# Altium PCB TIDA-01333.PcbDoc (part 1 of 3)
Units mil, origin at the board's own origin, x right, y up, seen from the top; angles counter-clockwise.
Board outline 6250 x 2150 mil, 4 copper layers (Top Layer, GND, VDD, Bottom Layer), stack 61.6 mil thick; 242 components, 144 nets, 711 pads, 252 vias.
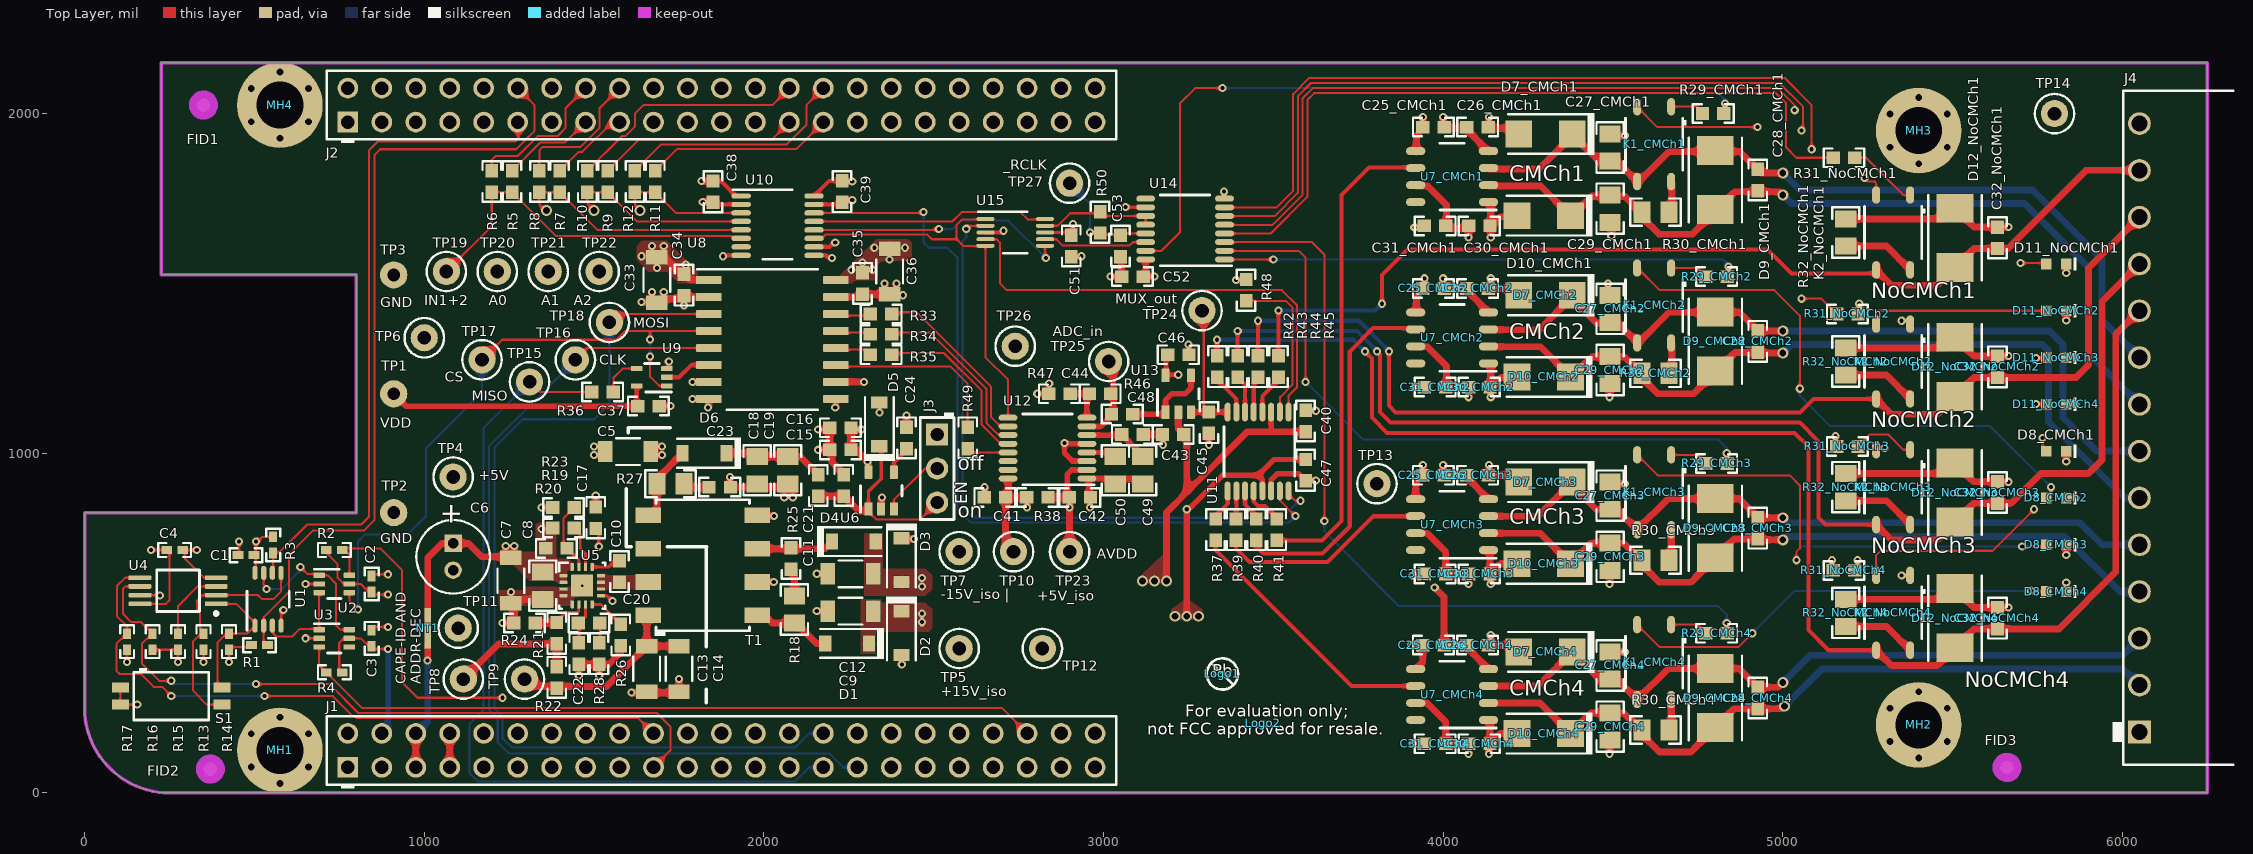
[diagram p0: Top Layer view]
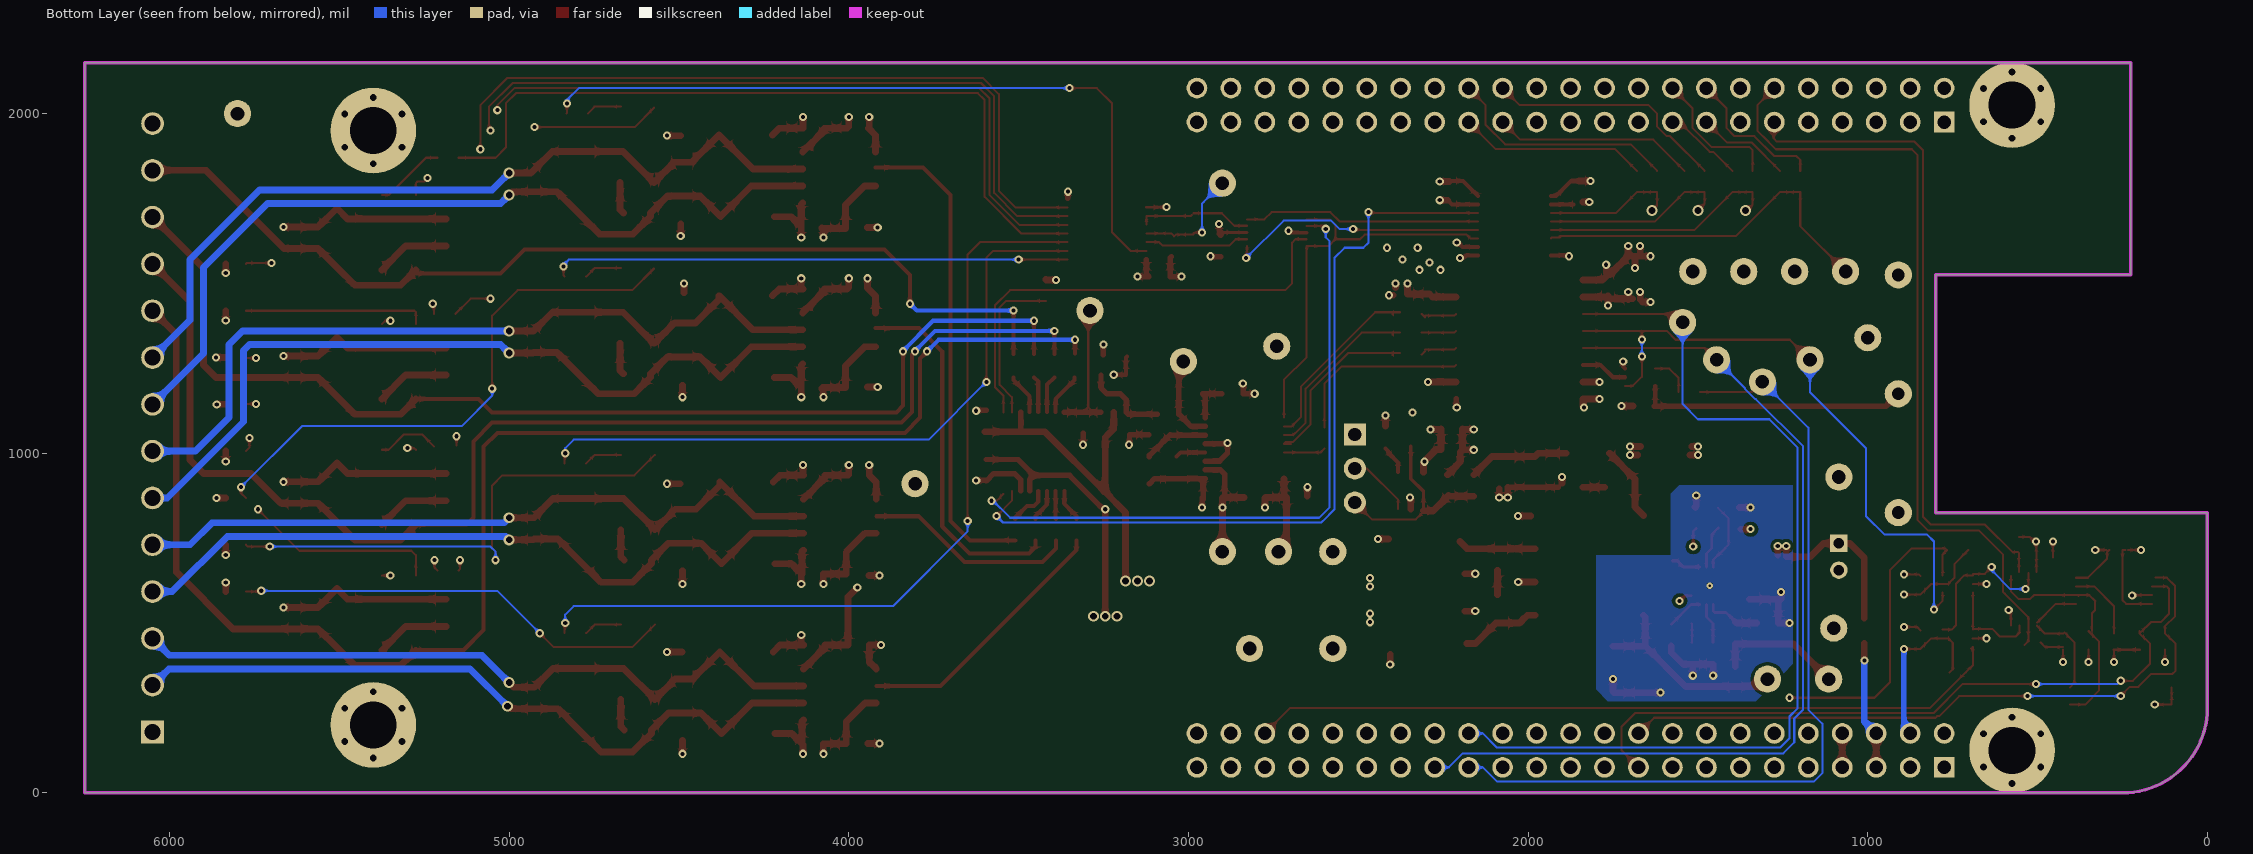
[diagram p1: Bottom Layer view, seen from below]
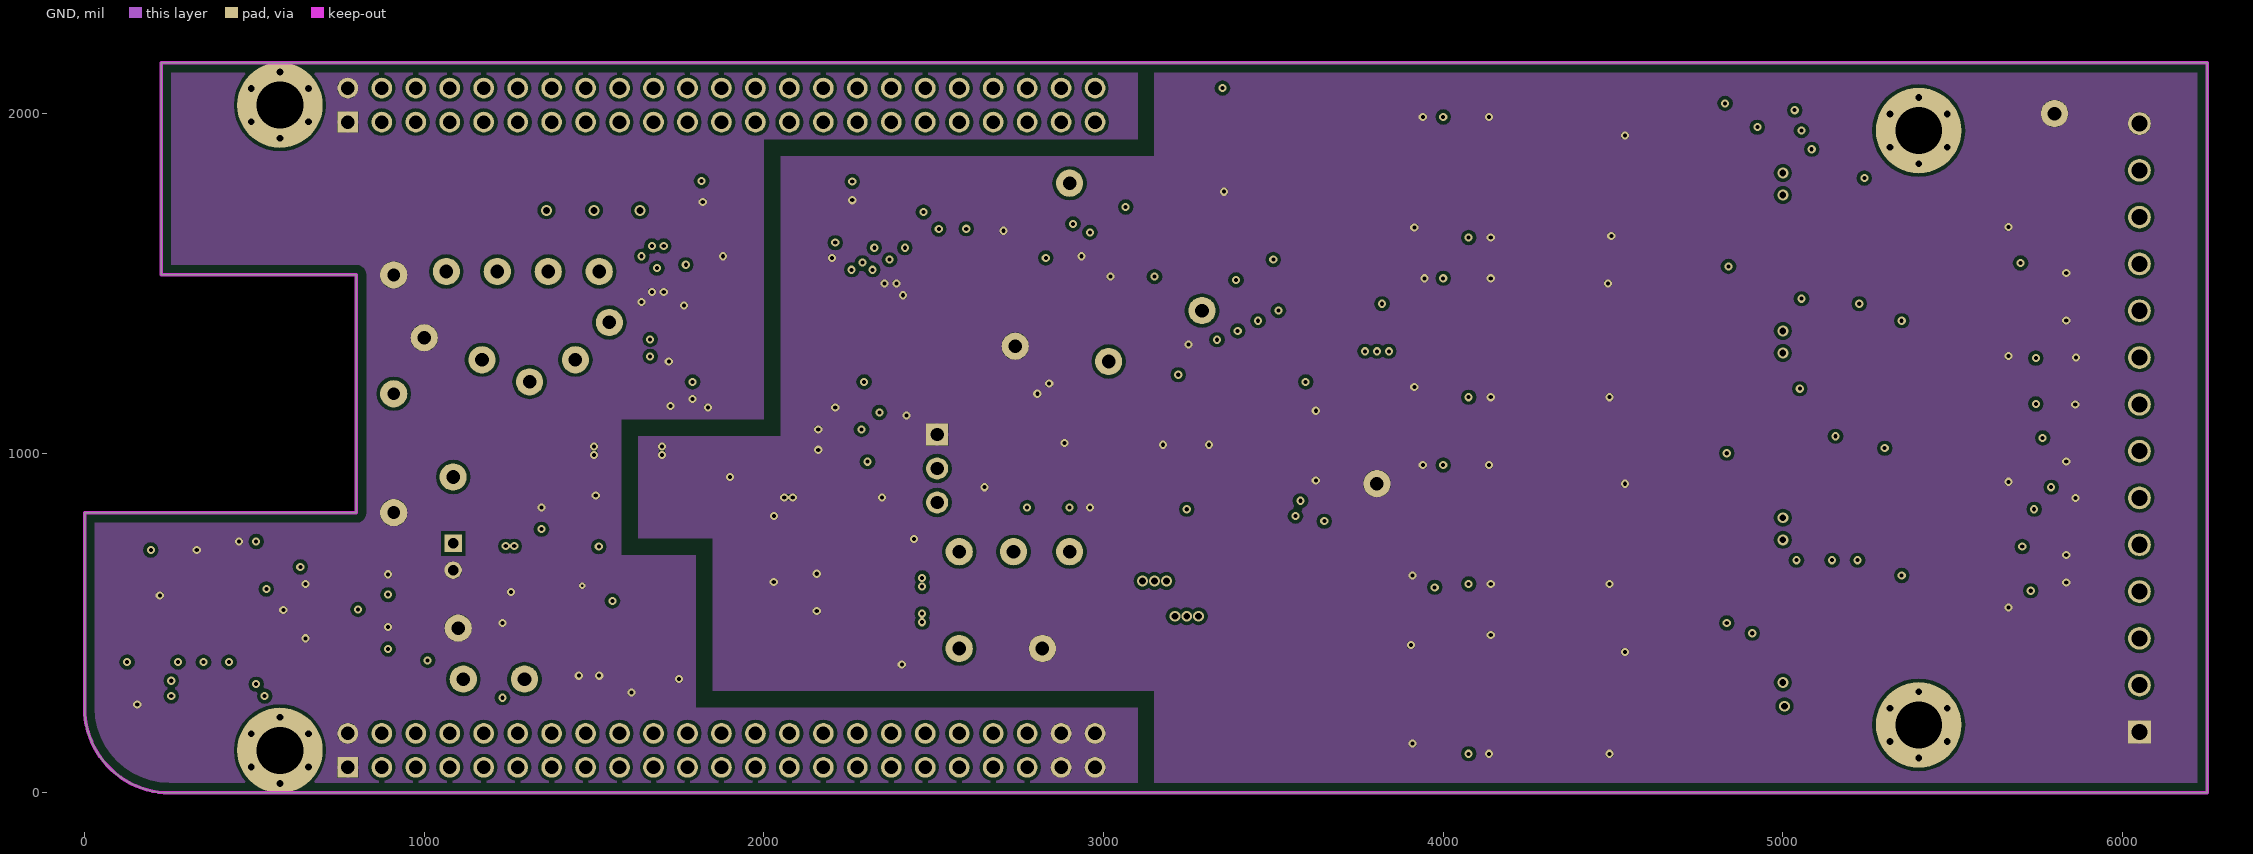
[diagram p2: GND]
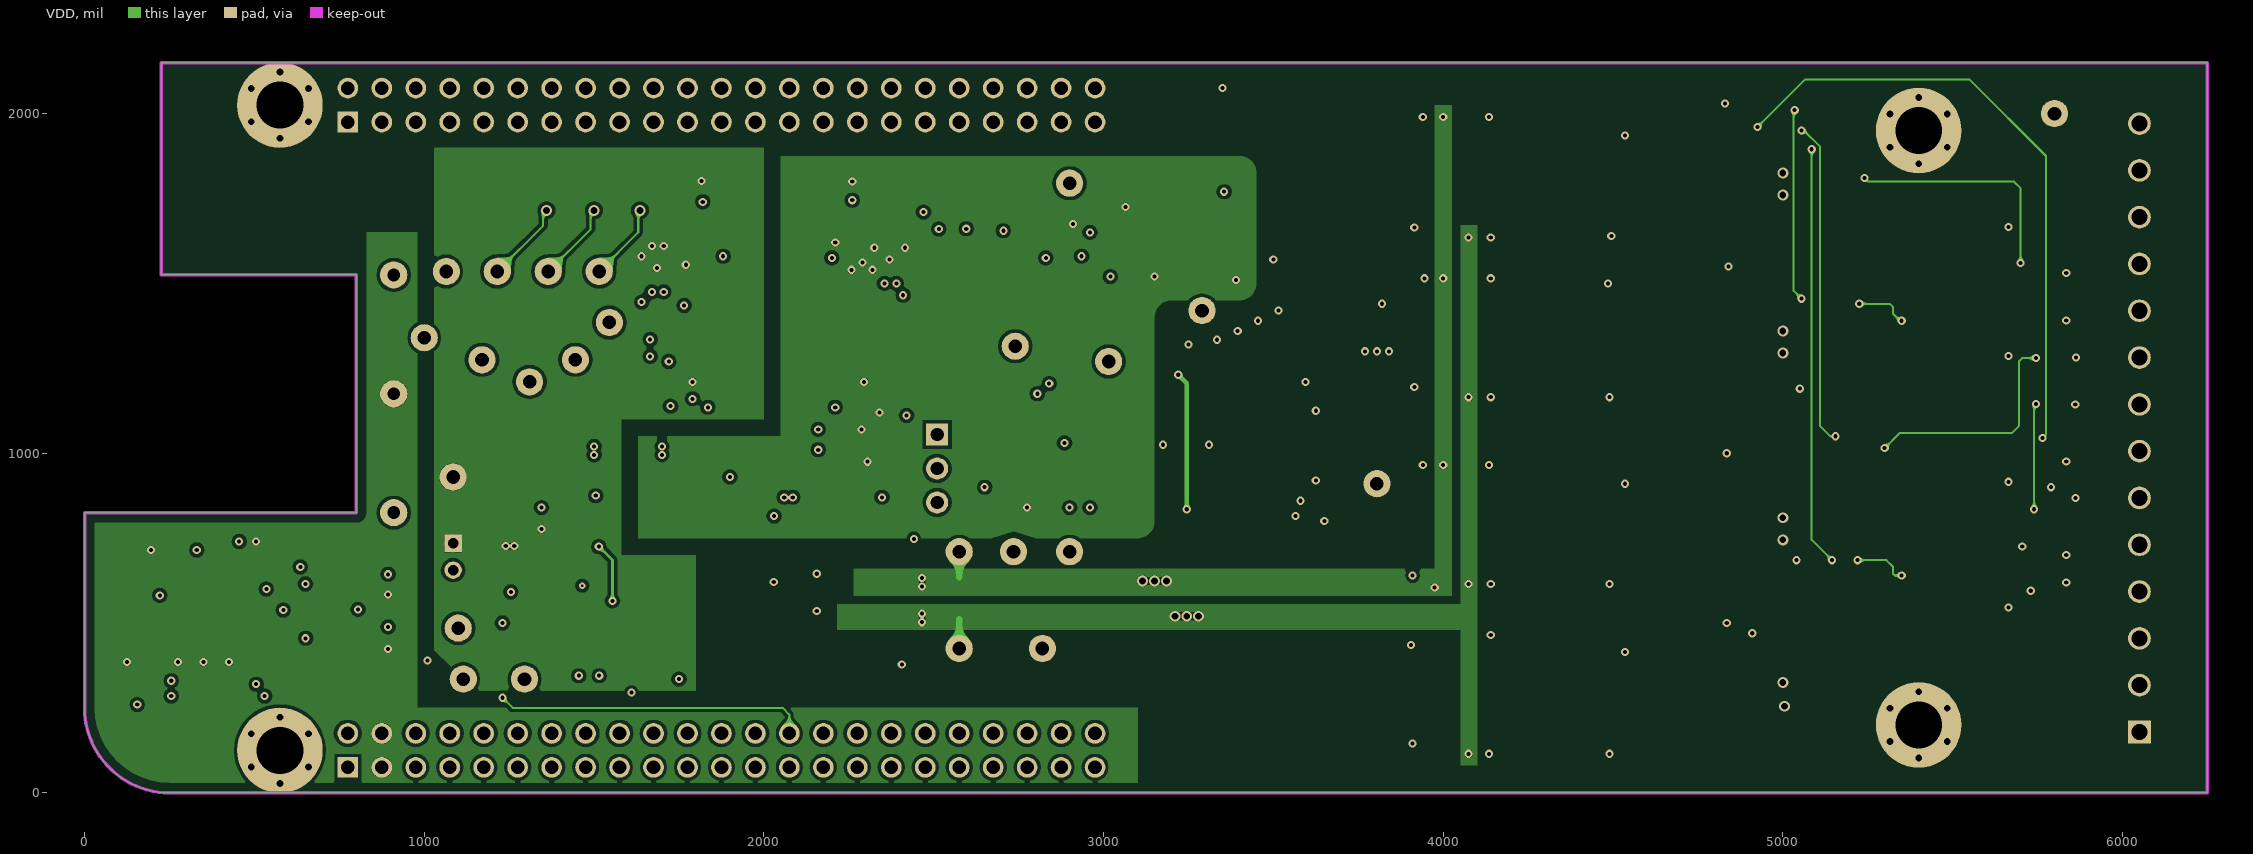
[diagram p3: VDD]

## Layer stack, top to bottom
Top Solder: solder mask 0.4, Solder Resist, Dk 3.5
Top Layer: signal copper 1.4
Dielectric 1: core 8, Dk 4.2
GND: signal copper 1.4
Dielectric 2: prepreg 40, FR-4, Dk 4.2
VDD: signal copper 1.4
Dielectric 3: core 8, Dk 4.2
Bottom Layer: signal copper 1.4
Bottom Solder: solder mask 0.4, Solder Resist, Dk 3.5

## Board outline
0,250 0,825 800,825 800,1525 225,1525 225,2150 6250,2150 6250,0 250,0 cw(c250,250)

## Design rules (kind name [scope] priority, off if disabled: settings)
AcuteAngle [All] p1: minimum=4.50000000000000E+0001 checktracksonly=FALSE
AssemblyTestPointUsage [All] p1: valid=2
Clearance Clearance_Keepouts [((IsTrack Or IsArc) And Not InPoly) And IsFree and IsKeepOut vs ((IsTrack Or IsArc) And Not InPoly) And IsFree and IsKeepOut] p1: gap=0
Clearance Clearance_BoardEdge_MountingHoles [OnCopper and InComponentClass('Mounting Holes') vs IsKeepOut] p2: gap=40
Clearance Clearance_BoardEdge_Poly [OnCopper and InPoly vs IsKeepOut] p3: gap=25
Clearance Clearance_BoardEdge [OnCopper and Not InComponentClass('Logo') and not InComponentClass('FiducialMark') and not InRegion(1000,500,4000,800) and Not IsKeepout vs IsKeepOut] p4: gap=25
Clearance Clearance_Poly [InPolygon] p5: gap=10
Clearance [All] p6: gap=7.87
ComponentClearance ISO-ISOW [InComponent('U10') vs InComponent('U8')] p1: gap=0 collisioncheckmode=3 verticalgap=0 showdistances=FALSE
ComponentClearance ComponentClearance_THtoTH_1 [HasFootprint('Major_BBB_SSHQ-123-D-08') vs HasFootprint('MTGP_4-40_PanHead')] p2: gap=0 collisioncheckmode=3 verticalgap=0 showdistances=FALSE
ComponentClearance ComponentClearance_MountingHoles_FiducialMarks [InComponentClass('Mounting Holes') vs InComponentClass('FiducialMark')] p3: gap=50 collisioncheckmode=3 verticalgap=10 showdistances=FALSE
ComponentClearance ComponentClearance_Shunt [InComponentClass('Header') vs InComponentClass('Shunt')] p4: gap=0 collisioncheckmode=3 verticalgap=0 showdistances=FALSE
ComponentClearance ComponentClearance_Logo [InComponentClass('Logo')] p5: gap=50 collisioncheckmode=3 verticalgap=10 showdistances=FALSE
ComponentClearance ComponentClearance_ScrewToNut [(HasFootprint('NY PMS 440 0025 PH')) vs (HasFootprint('Keystone_1902C'))] p6: gap=5 collisioncheckmode=3 verticalgap=10 showdistances=FALSE
ComponentClearance ComponentClearance_MountingHoles [InComponentClass('Mounting Holes')] p7: gap=250 collisioncheckmode=3 verticalgap=100000 showdistances=FALSE
ComponentClearance ComponentClearance_SmallPassives [HasFootprint('0201*') or HasFootprint('0402*') or HasFootprint('0508') or HasFootprint('0603*') or HasFootprint('0612') or HasFootprint('0805*') or HasFootprint('0815*') or HasFootprint('0830*') or HasFootprint('1206*') or HasFootprint('1210*') or HasFootprint('1808*') or HasFootprint('1812*') or HasFootprint('1825*') or HasFootprint('2010*') or HasFootprint('2220*') or HasFootprint('2225*') or HasFootprint('2512*') or HasFootprint('2728*') or HasFootprint('3518*') vs HasFootprint('0201*') or HasFootprint('0402*') or HasFootprint('0508') or HasFootprint('0603*') or HasFootprint('0612') or HasFootprint('0805*') or HasFootprint('0815*') or HasFootprint('0830*') or HasFootprint('1206*') or HasFootprint('1210*') or HasFootprint('1808*') or HasFootprint('1812*') or HasFootprint('1825*') or HasFootprint('2010*') or HasFootprint('2220*') or HasFootprint('2225*') or HasFootprint('2512*') or HasFootprint('2728*') or HasFootprint('3518*')] p8: gap=20 collisioncheckmode=3 verticalgap=10 showdistances=FALSE
ComponentClearance ComponentClearance_THtoSMT [IsThruComponent vs IsSMTComponent] p9: gap=20 collisioncheckmode=3 verticalgap=30 showdistances=FALSE
ComponentClearance ComponentClearance_THtoTH [IsThruComponent vs IsThruComponent] p10: gap=50 collisioncheckmode=3 verticalgap=20 showdistances=FALSE
ComponentClearance ComponentClearance_1 [All] p11: gap=10 collisioncheckmode=3 verticalgap=10 showdistances=FALSE
DiffPairsRouting [All] p1: maxlimit=100 minlimit=10 mostfreqgap=10 toplayer_minwidth=15 toplayer_maxwidth=15 toplayer_prefwidth=15 midlayer1_minwidth=15 midlayer1_maxwidth=15 midlayer1_prefwidth=15 midlayer2_minwidth=15 midlayer2_maxwidth=15 midlayer2_prefwidth=15 bottomlayer_minwidth=15 bottomlayer_maxwidth=15 bottomlayer_prefwidth=15 maxuncoupledlength=1000
FabricationTestPointUsage TestPointUsage [All] p1: valid=2 allowmultiple=FALSE
FabricationTestpoint Testpoint [All] p1: side=3 testpointundercomponent=TRUE minsize=40 maxsize=100 preferedsize=60 minholesize=0 maxholesize=40 preferedholesize=32 testpointgrid=1 allowsidetop=TRUE allowsidebottom=TRUE usegrid=TRUE gridtolerance=0.01
FanoutControl Fanout_LCC [IsLCC] p1: bgadir=Out bgaviamode=Centered fanoutstyle=Auto fanoutdirection=Alternating viagrid=1 // Fanout_LCC (Default Rule)
FanoutControl Fanout_BGA [IsBGA] p2: bgadir=Out bgaviamode=Centered fanoutstyle=Auto fanoutdirection=Alternating viagrid=1 // Fanout_BGA (Default Rule)
FanoutControl Fanout_Default [All] p4: bgadir=Out bgaviamode=Centered fanoutstyle=Auto fanoutdirection=Alternating viagrid=1 // Fanout_Default (Default Rule)
FanoutControl Fanout_Small [(CompPinCount < 5)] p5: bgadir=Out bgaviamode=Centered fanoutstyle=Auto fanoutdirection=OutThenIn viagrid=1 // Fanout_Small (Default Rule)
HoleSize [All] p1: absolutevalues=TRUE maxlimit=251 minlimit=8 maxpercent=80.000 minpercent=20.000
MinimumAnnularRing MinimumAnnularRing_ThermalPadVias [IsVia and InAnyComponent] p1: minimumring=5.91
MinimumAnnularRing [All] p2: minimumring=6
MinimumSolderMaskSliver MinimumSolderMaskSliver_Logo [InComponentClass('Logo') vs InComponentClass('Logo')] p1: minsoldermaskwidth=0.7
MinimumSolderMaskSliver [All] p2: minsoldermaskwidth=3.94
PlaneConnect [All] p1: planeconnectstyle=Direct reliefexpansion=10 reliefentries=4 reliefconductorwidth=10 reliefairgap=10
PolygonConnect PolygonConnect_12 [All vs IsNamedPolygon('GND_CH1_AVDD')] p1: connectstyle=Direct reliefconductorwidth=10 reliefentries=4 polygonreliefangle="90 Angle" airgapwidth=10
PolygonConnect PolygonConnect_11 [All vs IsNamedPolygon('GND_CH1_AVSS')] p2: connectstyle=Direct reliefconductorwidth=10 reliefentries=4 polygonreliefangle="90 Angle" airgapwidth=10
PolygonConnect PolygonConnect_10 [All vs IsNamedPolygon('LOCALTEMP_CH2_P')] p3: connectstyle=Direct reliefconductorwidth=10 reliefentries=4 polygonreliefangle="90 Angle" airgapwidth=10
PolygonConnect PolygonConnect_9 [All vs IsNamedPolygon('LOCALTEMP_CH1_P')] p4: connectstyle=Direct reliefconductorwidth=10 reliefentries=4 polygonreliefangle="90 Angle" airgapwidth=10
PolygonConnect PolygonConnect_8 [All vs IsNamedPolygon('LOCALTEMP_CH1_N')] p5: connectstyle=Direct reliefconductorwidth=10 reliefentries=4 polygonreliefangle="90 Angle" airgapwidth=10
PolygonConnect PolygonConnect_7 [All vs IsNamedPolygon('LOCALTEMP_CH2_N')] p6: connectstyle=Direct reliefconductorwidth=10 reliefentries=4 polygonreliefangle="90 Angle" airgapwidth=10
PolygonConnect PolygonConnect_6 [All vs IsNamedPolygon('LOCALTEMP_N')] p7: connectstyle=Direct reliefconductorwidth=10 reliefentries=4 polygonreliefangle="90 Angle" airgapwidth=10
PolygonConnect PolygonConnect_5 [All vs IsNamedPolygon('LOCALTEMP_P')] p8: connectstyle=Direct reliefconductorwidth=10 reliefentries=4 polygonreliefangle="90 Angle" airgapwidth=10
PolygonConnect PolygonConnect_4 [All vs IsNamedPolygon('LOCALTEMP_N')] p9: connectstyle=Direct reliefconductorwidth=10 reliefentries=4 polygonreliefangle="90 Angle" airgapwidth=10
PolygonConnect PolygonConnect_3 [All vs IsNamedPolygon('V--No Net')] p10: connectstyle=Relief reliefconductorwidth=10 reliefentries=4 polygonreliefangle="90 Angle" airgapwidth=10
PolygonConnect PolygonConnect_2 [All vs IsNamedPolygon('Bottom Layer-GND')] p11: connectstyle=Direct reliefconductorwidth=10 reliefentries=4 polygonreliefangle="90 Angle" airgapwidth=10
PolygonConnect PolygonConnect_1 [All vs IsNamedPolygon('Top Layer-No Net')] p12: connectstyle=Relief reliefconductorwidth=10 reliefentries=4 polygonreliefangle="90 Angle" airgapwidth=10
PolygonConnect [All vs IsNamedPolygon('Top Layer-VCC')] p13: connectstyle=Relief reliefconductorwidth=10 reliefentries=4 polygonreliefangle="90 Angle" airgapwidth=10
RoomDefinition NoCMCh4 [InComponentClass('NoCMCh4')] p1: confinementstyle=ConfineIn formatcopy=TRUE lockcomponents=TRUE outline 5680,360 5110,360 5110,675 5680,675
RoomDefinition NoCMCh3 [InComponentClass('NoCMCh3')] p2: confinementstyle=ConfineIn formatcopy=TRUE lockcomponents=TRUE outline 5680,730 5110,730 5110,1045 5680,1045
RoomDefinition NoCMCh2 [InComponentClass('NoCMCh2')] p3: confinementstyle=ConfineIn formatcopy=TRUE lockcomponents=TRUE outline 5680,1100 5110,1100 5110,1415 5680,1415
RoomDefinition NoCMCh1 [InComponentClass('NoCMCh1')] p4: confinementstyle=ConfineIn formatcopy=TRUE lockcomponents=TRUE outline 5680,1480 5110,1480 5110,1795 5680,1795
RoomDefinition CMCh4 [InComponentClass('CMCh4')] p5: confinementstyle=ConfineIn formatcopy=TRUE lockcomponents=FALSE outline 3875,530 4970,530 4970,95 3875,95
RoomDefinition CMCh3 [InComponentClass('CMCh3')] p6: confinementstyle=ConfineIn formatcopy=TRUE lockcomponents=FALSE outline 3875,1030 4970,1030 4970,595 3875,595
RoomDefinition CMCh2 [InComponentClass('CMCh2')] p7: confinementstyle=ConfineIn formatcopy=TRUE lockcomponents=FALSE outline 3875,1580 4970,1580 4970,1145 3875,1145
RoomDefinition CMCh1 [InComponentClass('CMCh1')] p8: confinementstyle=ConfineIn formatcopy=TRUE lockcomponents=FALSE outline 3875,2055 4970,2055 4970,1620 3875,1620
RoutingVias ThermalPadVias [IsVia and InAnyComponent] p1: holewidth=7.87 width=19.68 viastyle="Through Hole" minholewidth=7.87 minwidth=19.68 maxholewidth=12.99 maxwidth=24
RoutingVias [All] p2: holewidth=12 width=24 viastyle="Through Hole" minholewidth=12 minwidth=24 maxholewidth=20 maxwidth=40
ShortCircuit ShortCircuit_MH [InPadClass('MHclass')] p1: allowed=TRUE
ShortCircuit [All] p2: allowed=FALSE
SilkToBoardRegionClearance [Not ((IsComment or IsDesignator) And (Hide <> 'False')) and not InRegion(1000,500,4000,800)] p1 off:
SilkToSilkClearance SilkToSilkClearance_Pb-FreeLogo [(HasFootprint('Pb-Free_Overlay_Medium') OR HasFootprint('Pb-Free_Overlay_Small')) vs (HasFootprint('Pb-Free_Overlay_Medium') OR HasFootprint('Pb-Free_Overlay_Small'))] p1 off: silktosilkclearance=0
SilkToSilkClearance [All] p2 off: silktosilkclearance=5
SilkToSolderMaskClearance "Silk to Solder Mask Opening" [All] p1 off: minsilkscreentomaskgap=1 clearancetoexposedcopper=FALSE
SolderMaskExpansion [All] p1: expansion=1.97
Width [All] p1: maxlimit=20 minlimit=6 preferedwidth=6 checkconnectedcopper=TRUE
14 further rules are at their usual default settings.

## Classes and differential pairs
component class AssemblyNote: ZZ1 ZZ2 ZZ3
component class FiducialMark: FID1 FID2 FID3
component class TIDA-01333_Cape: C1 C2 C3 C4 J1 J2 NT1 R1 R2 R3 R4 R5 R6 R7 R8 R9 R10 R11 R12 R13 R14 R15 R16 R17 S1 TP1 TP2 TP3 U1 U2 U3 U4
component class U_TIDA-00764_Hardware: FID1 FID2 FID3 Logo1 Logo2 MH1 MH2 MH3 MH4 ZZ1 ZZ2 ZZ3
component class CMCh1: C6_CMCh1 C7_CMCh1 C8_CMCh1 C9_CMCh1 C10_CMCh1 C11_CMCh1 C25_CMCh1 C26_CMCh1 C27_CMCh1 C28_CMCh1 C29_CMCh1 C30_CMCh1 C31_CMCh1 D5_CMCh1 D7_CMCh1 D8 D8_CMCh1 D9_CMCh1 D10_CMCh1 K1_CMCh1 R29_CMCh1 R30_CMCh1 U7_CMCh1
component class CMCh2: C25_CMCh2 C26_CMCh2 C27_CMCh2 C28_CMCh2 C29_CMCh2 C30_CMCh2 C31_CMCh2 D7_CMCh2 D8_CMCh2 D9_CMCh2 D10_CMCh2 K1_CMCh2 R29_CMCh2 R30_CMCh2 U7_CMCh2
component class CMCh3: C25_CMCh3 C26_CMCh3 C27_CMCh3 C28_CMCh3 C29_CMCh3 C30_CMCh3 C31_CMCh3 D7_CMCh3 D8_CMCh3 D9_CMCh3 D10_CMCh3 K1_CMCh3 R29_CMCh3 R30_CMCh3 U7_CMCh3
component class CMCh4: C25_CMCh4 C26_CMCh4 C27_CMCh4 C28_CMCh4 C29_CMCh4 C30_CMCh4 C31_CMCh4 D7_CMCh4 D8_CMCh4 D9_CMCh4 D10_CMCh4 K1_CMCh4 R29_CMCh4 R30_CMCh4 U7_CMCh4
component class Digital_Isolation: C33 C34 C35 C36 C37 C38 C39 R33 R34 R35 R36 TP15 TP16 TP17 TP18 TP19 TP20 TP21 TP22 U8 U9 U10
component class MUX_Stage: C40 C41 C42 C43 C44 C45 C46 C47 C48 C49 C50 C51 C52 C53 R37 R38 R39 R40 R41 R42 R43 R44 R45 R46 R47 R48 R49 R50 TP23 TP24 TP25 TP26 TP27 U11 U12 U13 U14 U15
component class NoCMCh1: C32_NoCMCh1 D2_NoCMCh1 D11_NoCMCh1 D12_NoCMCh1 K2_NoCMCh1 R31_NoCMCh1 R32_NoCMCh1
component class NoCMCh2: C32_NoCMCh2 D11_NoCMCh2 D12_NoCMCh2 K2_NoCMCh2 R31_NoCMCh2 R32_NoCMCh2
component class NoCMCh3: C32_NoCMCh3 D11_NoCMCh3 D12_NoCMCh3 K2_NoCMCh3 R31_NoCMCh3 R32_NoCMCh3
component class NoCMCh4: C32_NoCMCh4 D11_NoCMCh4 D12_NoCMCh4 K2_NoCMCh4 R31_NoCMCh4 R32_NoCMCh4
component class U_TIDA-00764_Power_Stage: C5 C6 C7 C8 C9 C10 C11 C12 C13 C14 C15 C16 C17 C18 C19 C20 C21 C22 C23 C24 D1 D2 D3 D4 D5 D6 J3 R18 R19 R20 R21 R22 R23 R24 R25 R26 R27 R28 SH-J1 T1 TP4 TP5 TP6 TP7 TP8 TP9 TP10 TP11 U5 U6
component class Header: J3
component class U_TIDA-00764_Signal_Chain: J4 TP12 TP13 TP14
channel class TIDA-01333_Ch_Input: NoCMCh1 NoCMCh2 NoCMCh3 NoCMCh4
channel class TIDA-01333_CMCh_Input: CMCh1 CMCh2 CMCh3 CMCh4

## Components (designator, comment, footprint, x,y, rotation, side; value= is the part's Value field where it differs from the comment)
C1 "C1005X7R1H104K050BB" 0402 475,700 r180 top
C2 "C1005X7R1H104K050BB" 0402 845,615 r90 top
C3 "C1005X7R1H104K050BB" 0402 845,455.02 r90 top
C4 "C1005X7R1H104K050BB" 0402 265,715 r0 top
C5 "202R18W102KV4E" 1206_190 1600,1005 r180 top
C6 "ECA-1VM470" CAPPRD200W50D500H1100 1085,695 r270 top
C7 "GRM31CR71A226KE15L" 1206_180 1255,625 r270 top
C8 "C2012X7R1A106K125AC" 0805_HV 1348.9,610 r90 top
C9 "GRM31CR71H225KA88L" 1206_180 2255,535 r180 top
C10 "GRM188R71H104KA93D" 0603 1574.87,651.38 r90 top
C11 "GRM1885C1H150JA01D" 0603 2080,690 r90 top
C12 "GRM31CR71H225KA88L" 1206_180 2255,645 r0 top
C13 "GRM31CR71A226KE15L" 1206_180 1655,365 r270 top
C14 "GRM31CR71A226KE15L" 1206_180 1750,365 r270 top
C15 "GRM188R71A225KE15D" 0603 2225,1010 r180 top
C16 "GRM188R71A225KE15D" 0603 2225,1075 r180 top
C17 "GRM188R71H104KA93D" 0603 1505,810 r90 top
C18 "C2012X7R1A106K125AC" 0805_HV 1980,950 r270 top
C19 "C2012X7R1A106K125AC" 0805_HV 2070,950 r90 top
C20 "GRM188R71H333KA61D" 0603 1485,500 r0 top
C21 "GRM188R71A225KE15D" 0603 2235,905 r90 top
C22 "GRM1885C1H820JA01D" 0603 1455,410 r90 top
C23 "GRM1885C1H150JA01D" 0603 1870,900 r0 top
C24 "06031C103KAT2A" 0603 2420,1045 r90 top
C25_CMCh1 "GRM188R71H104KA93D" 0603 3971.26,1960 r0 top (schematic designator C25)
C25_CMCh2 "GRM188R71H104KA93D" 0603 3971.26,1485 r0 top (schematic designator C25)
C25_CMCh3 "GRM188R71H104KA93D" 0603 3971.26,935 r0 top (schematic designator C25)
C25_CMCh4 "GRM188R71H104KA93D" 0603 3971.26,435 r0 top (schematic designator C25)
C26_CMCh1 "C1608X7R1C105K080AC" 0603 4101.26,1960 r180 top (schematic designator C26)
C26_CMCh2 "C1608X7R1C105K080AC" 0603 4101.26,1485 r180 top (schematic designator C26)
C26_CMCh3 "C1608X7R1C105K080AC" 0603 4101.26,935 r180 top (schematic designator C26)
C26_CMCh4 "C1608X7R1C105K080AC" 0603 4101.26,435 r180 top (schematic designator C26)
C27_CMCh1 "C0805C102JBRACTU" 0805_HV 4491.26,1900 r90 top (schematic designator C27)
C27_CMCh2 "C0805C102JBRACTU" 0805_HV 4491.26,1425 r90 top (schematic designator C27)
C27_CMCh3 "C0805C102JBRACTU" 0805_HV 4491.26,875 r90 top (schematic designator C27)
C27_CMCh4 "C0805C102JBRACTU" 0805_HV 4491.26,375 r90 top (schematic designator C27)
C28_CMCh1 "06031C103KAT2A" 0603 4926.26,1804.28 r270 top (schematic designator C28)
C28_CMCh2 "06031C103KAT2A" 0603 4926.26,1329.28 r270 top (schematic designator C28)
C28_CMCh3 "06031C103KAT2A" 0603 4926.26,779.28 r270 top (schematic designator C28)
C28_CMCh4 "06031C103KAT2A" 0603 4926.26,279.28 r270 top (schematic designator C28)
C29_CMCh1 "C0805C102JBRACTU" 0805_HV 4491.26,1720 r90 top (schematic designator C29)
C29_CMCh2 "C0805C102JBRACTU" 0805_HV 4491.26,1245 r90 top (schematic designator C29)
C29_CMCh3 "C0805C102JBRACTU" 0805_HV 4491.26,695 r90 top (schematic designator C29)
C29_CMCh4 "C0805C102JBRACTU" 0805_HV 4491.26,195 r90 top (schematic designator C29)
C30_CMCh1 "GRM188R71H104KA93D" 0603 4106.26,1669.51 r0 top (schematic designator C30)
C30_CMCh2 "GRM188R71H104KA93D" 0603 4106.26,1194.51 r0 top (schematic designator C30)
C30_CMCh3 "GRM188R71H104KA93D" 0603 4106.26,644.51 r0 top (schematic designator C30)
C30_CMCh4 "GRM188R71H104KA93D" 0603 4106.26,144.51 r0 top (schematic designator C30)
C31_CMCh1 "C1608X7R1C105K080AC" 0603 3976.26,1669.51 r180 top (schematic designator C31)
C31_CMCh2 "C1608X7R1C105K080AC" 0603 3976.26,1194.51 r180 top (schematic designator C31)
C31_CMCh3 "C1608X7R1C105K080AC" 0603 3976.26,644.51 r180 top (schematic designator C31)
C31_CMCh4 "C1608X7R1C105K080AC" 0603 3976.26,144.51 r180 top (schematic designator C31)
C32_NoCMCh1 "06031C103KAT2A" 0603 5632,1634.32 r90 top (schematic designator C32)
C32_NoCMCh2 "06031C103KAT2A" 0603 5632,1254.32 r90 top (schematic designator C32)
C32_NoCMCh3 "06031C103KAT2A" 0603 5632,884.32 r90 top (schematic designator C32)
C32_NoCMCh4 "06031C103KAT2A" 0603 5632,514.32 r90 top (schematic designator C32)
C33 "GRM31CR71A226KE15L" 1206_180 1685,1510 r270 top
C34 "GRM188R71H104KA93D" 0603 1765,1495 r270 top
C35 "GRM188R71H104KA93D" 0603 2290,1500 r270 top
C36 "GRM31CR71A226KE15L" 1206_180 2370,1535 r270 top
C37 "GRM188R71H104KA93D" 0603 1660,1138.68 r0 top
C38 "GRM188R71H104KA93D" 0603 1850,1770 r270 top
C39 "GRM188R71H104KA93D" 0603 2230.32,1770.32 r270 top
C40 "GRM188R71H104KA93D" 0603 3595,1095 r270 top
C41 "C1608X7R1C105K080AC" 0603 2680,870 r180 top
C42 "C1608X7R1C105K080AC" 0603 2930,870 r0 top
C43 "GRM188R71H104KA93D" 0603 3205,1055 r0 top
C44 "GRM1885C1H101JA01D" 0603 2990,1175 r180 top
C45 "GRM1885C1H821JA01D" 0603 3310,1090 r270 top
C46 "GRM188R71H104KA93D" 0603 3220,1290 r0 top
C47 "GRM188R71H104KA93D" 0603 3595,950 r270 top
C48 "C1608X7R1C105K080AC" 0603 3085,1055 r0 top
C49 "C2012X7R1A106K125AC" 0805_HV 3115,950 r90 top
C50 "C2012X7R1A106K125AC" 0805_HV 3035,950 r90 top
C51 "GRM188R71H104KA93D" 0603 2905,1610 r270 top
C52 "GRM188R71H104KA93D" 0603 3085,1520 r180 top
C53 "GRM188R71H104KA93D" 0603 3050,1610 r270 top
D1 "BAT41ZFILM" SOD-123 2245,440 r180 top
D2 "MMSZ4703T1G" SOD-123 2405,470 r270 top
D3 "MMSZ4703T1G" SOD-123 2405,685 r270 top
D4 "BAT41ZFILM" SOD-123 2265,740 r0 top
D5 "B0530W-7-F" SOD-123 2340,1085 r90 top
D6 "B0530W-7-F" SOD-123 1825,1000 r180 top
D7_CMCh1 "SMAJ160CA" SMA 4301.26,1940 r180 top (schematic designator D7)
D7_CMCh2 "SMAJ160CA" SMA 4301.26,1465 r180 top (schematic designator D7)
D7_CMCh3 "SMAJ160CA" SMA 4301.26,915 r180 top (schematic designator D7)
D7_CMCh4 "SMAJ160CA" SMA 4301.26,415 r180 top (schematic designator D7)
D8_CMCh1 "LB Q39G-L2N2-35-1" "LB Q39G_BLUE" 5805.01,1006.11 r0 top locked (schematic designator D8)
D8_CMCh2 "LB Q39G-L2N2-35-1" "LB Q39G_BLUE" 5805,868.32 r0 top locked (schematic designator D8)
D8_CMCh3 "LB Q39G-L2N2-35-1" "LB Q39G_BLUE" 5805,730.51 r0 top locked (schematic designator D8)
D8_CMCh4 "LB Q39G-L2N2-35-1" "LB Q39G_BLUE" 5805,592.72 r0 top locked (schematic designator D8)
D9_CMCh1 "SM6T36CA" SMB-Bi 4801.26,1804.28 r90 top (schematic designator D9)
D9_CMCh2 "SM6T36CA" SMB-Bi 4801.26,1329.28 r90 top (schematic designator D9)
D9_CMCh3 "SM6T36CA" SMB-Bi 4801.26,779.28 r90 top (schematic designator D9)
D9_CMCh4 "SM6T36CA" SMB-Bi 4801.26,279.28 r90 top (schematic designator D9)
D10_CMCh1 "SMAJ160CA" SMA 4296.26,1699.51 r180 top (schematic designator D10)
D10_CMCh2 "SMAJ160CA" SMA 4296.26,1224.51 r180 top (schematic designator D10)
D10_CMCh3 "SMAJ160CA" SMA 4296.26,674.51 r180 top (schematic designator D10)
D10_CMCh4 "SMAJ160CA" SMA 4296.26,174.51 r180 top (schematic designator D10)
D11_NoCMCh1 "LB Q39G-L2N2-35-1" "LB Q39G_BLUE" 5805,1557.28 r0 top locked (schematic designator D11)
D11_NoCMCh2 "LB Q39G-L2N2-35-1" "LB Q39G_BLUE" 5805,1419.49 r0 top locked (schematic designator D11)
D11_NoCMCh3 "LB Q39G-L2N2-35-1" "LB Q39G_BLUE" 5805,1281.69 r0 top locked (schematic designator D11)
D11_NoCMCh4 "LB Q39G-L2N2-35-1" "LB Q39G_BLUE" 5805,1143.9 r0 top locked (schematic designator D11)
D12_NoCMCh1 "SM6T36CA" SMB-Bi 5507,1634.32 r270 top (schematic designator D12)
D12_NoCMCh2 "SM6T36CA" SMB-Bi 5507,1254.32 r270 top (schematic designator D12)
D12_NoCMCh3 "SM6T36CA" SMB-Bi 5507,884.32 r270 top (schematic designator D12)
D12_NoCMCh4 "SM6T36CA" SMB-Bi 5507,514.32 r270 top (schematic designator D12)
FID1 "Fiducial" Fiducial10-20 350,2025 r0 top locked
FID2 "Fiducial" Fiducial10-20 370,70 r0 top locked
FID3 "Fiducial" Fiducial10-20 5660,75 r0 top locked
J1 "SSHQ-123-D-08-F-LF" Major_BBB_SSHQ-123-D-08 1875,125 r0 top locked
J2 "SSHQ-123-D-08-F-LF" Major_BBB_SSHQ-123-D-08 1875,2025 r0 top locked
J3 "5-146278-3" TE_5-146278-3 2510,955 r270 top
J4 "1844333" Phoenix_1844333 6365,1075 r180 top locked
K1_CMCh1 "CPC1017N" RELAY_CPC1017N 4621.26,1910 r270 top (schematic designator K1)
K1_CMCh2 "CPC1017N" RELAY_CPC1017N 4621.26,1435 r270 top (schematic designator K1)
K1_CMCh3 "CPC1017N" RELAY_CPC1017N 4621.26,885 r270 top (schematic designator K1)
K1_CMCh4 "CPC1017N" RELAY_CPC1017N 4621.26,385 r270 top (schematic designator K1)
K2_NoCMCh1 "CPC1017N" RELAY_CPC1017N 5325,1650 r270 top (schematic designator K2)
K2_NoCMCh2 "CPC1017N" RELAY_CPC1017N 5325,1270 r270 top (schematic designator K2)
K2_NoCMCh3 "CPC1017N" RELAY_CPC1017N 5325,900 r270 top (schematic designator K2)
K2_NoCMCh4 "CPC1017N" RELAY_CPC1017N 5325,530 r270 top (schematic designator K2)
Logo1 "Pb-Free Symbol" Pb-Free_Overlay_Small 3350,350 r0 top
Logo2 "FCC disclaimer" FCC_disclaimer_stacked 3470,205 r0 top
MH1 "MTG_Pads" MTGP_4-40_PanHead 575,125 r0 top locked
MH2 "MTG_Pads" MTGP_4-40_PanHead 5400,200 r0 top locked
MH3 "MTG_Pads" MTGP_4-40_PanHead 5400,1950 r0 top locked
MH4 "MTG_Pads" MTGP_4-40_PanHead 575,2025 r0 top locked
NT1 "Net-Tie" Net-Tie_20milWide_60milLong 1010,485 r90 top net-tie
R1 "CRCW040247K0JNED" 0402 515,435 r0 top
R2 "CRCW040247K0JNED" 0402 735.02,715.01 r0 top
R3 "CRCW040247K0JNED" 0402 555,730 r270 top
R4 "CRCW040247K0JNED" 0402 735,355 r180 top
R5 "CRCW06030000Z0EA" 0603 1258.7,1800 r270 top
R6 "CRCW06030000Z0EA" 0603 1198.7,1800 r270 top
R7 "CRCW06030000Z0EA" 0603 1398.68,1800 r270 top
R8 "CRCW06030000Z0EA" 0603 1338.68,1800 r270 top
R9 "CRCW06030000Z0EA" 0603 1540,1800 r270 top
R10 "CRCW06030000Z0EA" 0603 1480,1800 r270 top
R11 "CRCW06030000Z0EA" 0603 1680,1800 r270 top
R12 "CRCW06030000Z0EA" 0603 1620,1800 r270 top
R13 "CRCW040247K0JNED" 0402 350.02,445.02 r90 top
R14 "CRCW040247K0JNED" 0402 425.02,445.01 r90 top
R15 "CRCW040247K0JNED" 0402 275.01,445.02 r90 top
R16 "CRCW04026K65FKED" 0402 200.01,445.02 r90 top
R17 "CRCW04026K65FKED" 0402 125.01,445.02 r90 top
R18 "ERJ-6GEYJ102V" 0805_HV 2090,540 r270 top
R19 "CRCW060310K0JNEA" 0603 1410,780 r180 top
R20 "CRCW0603220KJNEA" 0603 1388.9,720 r180 top
R21 "CRCW060316K2FKEA" 0603 1390,470 r90 top
R22 "CRCW060349R9FKEA" 0603 1390,340 r270 top
R23 "CRCW060375K0JNEA" 0603 1410,840 r0 top
R24 "CRCW060310K0FKEA" 0603 1295,500 r0 top
R25 "CRCW06030000Z0EA" 0603 2160,905 r270 top
R26 "CRCW0603240KJNEA" 0603 1578.55,464.8 r90 top
R27 "ERJ-6GEYJ102V" 0805_HV 1725,910 r180 top
R28 "CRCW060310K0JNEA" 0603 1515,410 r90 top
R29_CMCh1 "CRCW0603180RJNEA" 0603 4795,2000 r0 top (schematic designator R29)
R29_CMCh2 "CRCW0603180RJNEA" 0603 4805,1520 r0 top (schematic designator R29)
R29_CMCh3 "CRCW0603180RJNEA" 0603 4805,970 r0 top (schematic designator R29)
R29_CMCh4 "CRCW0603180RJNEA" 0603 4805,470 r0 top (schematic designator R29)
R30_CMCh1 "RG2012P-201-B-T5" 0805_HV 4625,1710 r0 top (schematic designator R30)
R30_CMCh2 "RG2012P-201-B-T5" 0805_HV 4625,1235 r0 top (schematic designator R30)
R30_CMCh3 "RG2012P-201-B-T5" 0805_HV 4625,685 r0 top (schematic designator R30)
R30_CMCh4 "RG2012P-201-B-T5" 0805_HV 4625,185 r0 top (schematic designator R30)
R31_NoCMCh1 "CRCW0603180RJNEA" 0603 5180,1870 r180 top (schematic designator R31)
R31_NoCMCh2 "CRCW0603180RJNEA" 0603 5190,1410 r180 top (schematic designator R31)
R31_NoCMCh3 "CRCW0603180RJNEA" 0603 5190,1020 r180 top (schematic designator R31)
R31_NoCMCh4 "CRCW0603180RJNEA" 0603 5180,655 r180 top (schematic designator R31)
R32_NoCMCh1 "RT0805BRD07200RL" 0805_HV 5185,1650 r270 top (schematic designator R32)
R32_NoCMCh2 "RT0805BRD07200RL" 0805_HV 5185,1270 r270 top (schematic designator R32)
R32_NoCMCh3 "RT0805BRD07200RL" 0805_HV 5185,900 r270 top (schematic designator R32)
R32_NoCMCh4 "RT0805BRD07200RL" 0805_HV 5185,530 r270 top (schematic designator R32)
R33 "CRCW060349R9FKEA" 0603 2345,1410 r0 top
R34 "CRCW060349R9FKEA" 0603 2345,1350 r0 top
R35 "CRCW060349R9FKEA" 0603 2345,1290 r0 top
R36 "CRCW060349R9FKEA" 0603 1525,1180 r0 top
R37 "CRCW06035K11FKEA" 0603 3330,775 r270 top
R38 "CRCW06030000Z0EA" 0603 2805,870 r0 top
R39 "CRCW06035K11FKEA" 0603 3390,775 r270 top
R40 "CRCW06035K11FKEA" 0603 3450,775 r270 top
R41 "CRCW06035K11FKEA" 0603 3510,775 r270 top
R42 "CRCW06035K11FKEA" 0603 3335,1255 r90 top
R43 "CRCW06035K11FKEA" 0603 3395,1255 r90 top
R44 "CRCW06035K11FKEA" 0603 3455,1255 r90 top
R45 "CRCW06035K11FKEA" 0603 3515,1255 r90 top
R46 "CRCW06030000Z0EA" 0603 3055,1115 r0 top
R47 "CRCW0603374RFKEA" 0603 2870,1175 r180 top
R48 "CRCW0603100KJNEA" 0603 3420,1480 r90 top
R49 "CRCW060349R9FKEA" 0603 2600,1045 r270 top
R50 "CRCW060347K0JNEA" 0603 2990,1680 r270 top
S1 "416131160802" SW_416131160802 255,285 r0 top
SH-J1 "60900213421" Wurth_60900213421 7171.95,84.96 r90 top
T1 "750316449" Wurth_750316170 1820,670 r90 top
TP1 "TESTPOINT" TESTPOINT 910,1175 r0 top
TP2 "TESTPOINT" TESTPOINT 910,825 r0 top
TP3 "TESTPOINT" TESTPOINT 910,1525 r0 top
TP4 "5000" Keystone5000 1085,930 r90 top
TP5 "5000" Keystone5000 2575,425 r90 top
TP6 "5001" Keystone5001 1000,1340 r90 top
TP7 "5000" Keystone5000 2575,710 r90 top
TP8 "5002" Keystone5002 1115,335 r90 top
TP9 "5004" Keystone5004 1295,335 r90 top
TP10 "5000" Keystone5000 2735,710 r90 top
TP11 "5001" Keystone5001 1100,485 r90 top
TP12 "5001" Keystone5001 2820,425 r90 top
TP13 "5001" Keystone5001 3805,910.31 r90 top
TP14 "5001" Keystone5001 5800,2000 r90 top
TP15 "5004" Keystone5004 1310,1210 r90 top
TP16 "5004" Keystone5004 1445,1275 r90 top
TP17 "5004" Keystone5004 1170,1275 r90 top
TP18 "5004" Keystone5004 1545,1385 r90 top
TP19 "5004" Keystone5004 1065,1535 r90 top
TP20 "5004" Keystone5004 1215,1535 r90 top
TP21 "5004" Keystone5004 1365,1535 r90 top
TP22 "5004" Keystone5004 1515,1535 r90 top
TP23 "5003" Keystone5003 2900,710 r90 top
TP24 "5004" Keystone5004 3290,1420 r90 top
TP25 "5004" Keystone5004 3015,1270 r90 top
TP26 "5001" Keystone5001 2740,1315 r90 top
TP27 "5004" Keystone5004 2900,1795 r90 top
U1 "SN74LVC2G86DCTR" DCT0008A_N 540,570.13 r90 top
U2 "SN74LVC1G332DCKR" DCK0006A_N 735,615 r0 top
U3 "SN74LVC1G332DCKR" DCK0006A_N 735.02,455.02 r0 top
U4 "24LC256-I/ST" TSSOP-8 275,595 r180 top
U5 "TPS55010RTER" RTE0016F 1465,610 r0 top
U6 "LP2985-50DBVR" DBV0005A_N 2345.32,890 r90 top
U7_CMCh1 "INA149AIDR" D0008A_N 4026.26,1814.51 r180 top (schematic designator U7)
U7_CMCh2 "INA149AIDR" D0008A_N 4026.26,1339.51 r180 top (schematic designator U7)
U7_CMCh3 "INA149AIDR" D0008A_N 4026.26,789.51 r180 top (schematic designator U7)
U7_CMCh4 "INA149AIDR" D0008A_N 4026.26,289.51 r180 top (schematic designator U7)
U8 "ISOW7841DWR" DW0016B_N 2025,1335 r0 top
U9 "SN74LV1T125DCKR" DCK0005A_N 1670,1223.68 r180 top
U10 "ISO7140CCDBQR" DBQ0016A_N 2040.32,1670 r0 top
U11 "MUX36S08IPWR" PW0016A_N 3455,1005 r270 top
U12 "ADS8681IPWR" PW0016A_N 2835,1015 r180 top
U13 "OPA192IDBVR" DBV0005A_N 3220,1175 r90 top
U14 "SN74AHC594PWR" PW0016A_N 3240,1660 r180 top
U15 "TS5A23157DGSR" DGS0010A_N 2740,1650 r0 top
ZZ1 "This Assembly Note will show in the PcbDoc and associated outputs" AssemblyNote 6688,2326 r90 top
ZZ2 "This Assembly Note will show in the PcbDoc and associated outputs" AssemblyNote 6508,2326 r90 top
ZZ3 "This Assembly Note will show in the PcbDoc and associated outputs" AssemblyNote 6325,2320 r90 top

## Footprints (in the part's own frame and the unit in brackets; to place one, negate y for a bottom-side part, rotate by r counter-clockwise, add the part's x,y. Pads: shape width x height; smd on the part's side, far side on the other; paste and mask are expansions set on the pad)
0402 [mm] "0402 from SM-752 data"
  rect 0.8x0.6 smd: 1(-0.6,0) 2(0.6,0)
  silkscreen extent -1.22,-0.52 1.22,0.52, body extent -0.55,-0.3 0.55,0.3, height 0.6
0603 [mm] "0603 from SM-752 data"
  rect 1x0.95 smd: 1(-0.8,0) 2(0.8,0)
  silkscreen extent -1.52,-0.69 1.52,0.69, body extent -0.87,-0.47 0.87,0.47, height 1
0805_HV [mil] "0805 with 30mil clearance between pads"
  rect 50x63 smd: 1(-40,0) 2(40,0)
  silkscreen extent -74,-40 74,40, body extent -43,-29 43,29, height 57
1206_180 [mm] "1206_180"
  rect 1.1x1.6 smd: 1(-1.7,0) 2(1.7,0)
  silkscreen extent -0.9,-1 0.9,1, body extent -1.75,-0.95 1.75,0.95, height 1.8
1206_190 [mm] "1206_190"
  rect 1.1x1.6 smd: 1(-1.7,0) 2(1.7,0)
  silkscreen extent -0.9,-1 0.9,1, body extent -1.75,-0.95 1.75,0.95, height 1.9
AssemblyNote [mil] "Assembly Note"
CAPPRD200W50D500H1100 [mm] "Panasonic"
  rect 1.3x1.3 hole 0.787: 1(-1,0)
  round 1.3 hole 0.787: 2(1,0)
  silkscreen extent -2.75,-2.75 2.75,2.75, body extent -2.73,-2.75 2.75,2.75, height 12.01
D0008A_N [mm] "SOIC, 8-Leads, Body 4.9x3.9mm, Pitch 1.27mm, IPC Medium Density"
  oval 1.45x0.6 smd: 1(-2.725,1.905) 2(-2.725,0.635) 3(-2.725,-0.635) 4(-2.725,-1.905) 5(2.725,-1.905) 6(2.725,-0.635) 7(2.725,0.635) 8(2.725,1.905)
  silkscreen extent -3.3,-2.5 0.9,2.5, body extent -3,-2.45 3,2.45, height 1.63
DBQ0016A_N [mm] "SOP, 16-Leads, Body 4.9x3.9mm, Pitch 0.635mm, IPC Medium Density"
  oval 1.45x0.4 smd: 1(-2.725,2.222) 2(-2.725,1.587) 3(-2.725,0.953) 4(-2.725,0.318) 5(-2.725,-0.318) 6(-2.725,-0.953) 7(-2.725,-1.587) 8(-2.725,-2.222) 9(2.725,-2.222) 10(2.725,-1.587) 11(2.725,-0.953) 12(2.725,-0.318) 13(2.725,0.318) 14(2.725,0.953) 15(2.725,1.587) 16(2.725,2.222)
  silkscreen extent -3.35,-2.5 1.1,2.68, body extent -3.01,-2.45 3.01,2.45, height 1.63
DBV0005A_N [mm] "SOT23, 5-Leads, Body 2.9x1.6mm, Pitch 0.95mm, Lead Span 2.8mm, IPC Medium Density"
  rrect17% 1x0.6 smd: 1(-1.375,0.95) 2(-1.375,0) 3(-1.375,-0.95) 4(1.375,-0.95) 5(1.375,0.95)
  silkscreen extent -1.63,-1.55 0.38,1.55, body extent -1.42,-1.46 1.42,1.46, height 1.09
DCK0005A_N [mm] "SOT353, 5-Leads, Body 2x1.3mm, Pitch 0.65mm, Lead Span 2.1mm, IPC Medium Density"
  rrect25% 0.85x0.4 smd: 1(-1.125,0.65) 2(-1.125,0) 3(-1.125,-0.65) 4(1.125,-0.65) 5(1.125,0.65)
  silkscreen extent -1.48,-1.02 0.55,1.1, body extent -1.14,-1 1.14,1, height 0.95
DCK0006A_N [mm] "SOT23, 6-Leads, Body 2x1.3mm, Pitch 0.65mm, Lead Span 2.1mm, IPC Medium Density"
  rrect25% 0.85x0.4 smd: 1(-1.125,0.65) 2(-1.125,0) 3(-1.125,-0.65) 4(1.125,-0.65) 5(1.125,0) 6(1.125,0.65)
  silkscreen extent -1.5,-1.09 0.51,1.09, body extent -1.14,-1 1.14,1, height 0.95
DCT0008A_N [mm] "TSOP, 8-Leads, Body 3x2.8mm, Pitch 0.65mm, IPC Medium Density"
  oval 1.05x0.4 smd: 1(-1.975,0.975) 2(-1.975,0.325) 3(-1.975,-0.325) 4(-1.975,-0.975) 5(1.975,-0.975) 6(1.975,-0.325) 7(1.975,0.325) 8(1.975,0.975)
  silkscreen extent -2.32,-1.57 0.6,1.58, body extent -2.01,-1.47 2.01,1.48, height 1.3
DGS0010A_N [mm] "TSSOP, 10-Leads, Body 3x3mm, Pitch 0.5mm, IPC Medium Density"
  oval 1.35x0.3 smd: 1(-2.225,1) 2(-2.225,0.5) 3(-2.225,0) 4(-2.225,-0.5) 5(-2.225,-1) 6(2.225,-1) 7(2.225,-0.5) 8(2.225,0) 9(2.225,0.5) 10(2.225,1)
  silkscreen extent -2.75,-1.55 0.9,1.55, body extent -2.45,-1.5 2.45,1.5, height 0.96
DW0016B_N [mm] "SOIC, 16-Leads, Body 10.5x7.6mm, Pitch 1.27mm, IPC Medium Density"
  rrect17% 1.9x0.6 smd: 1(-4.75,4.445) 2(-4.75,3.175) 3(-4.75,1.905) 4(-4.75,0.635) 5(-4.75,-0.635) 6(-4.75,-1.905) 7(-4.75,-3.175) 8(-4.75,-4.445) 9(4.75,-4.445) 10(4.75,-3.175) 11(4.75,-1.905) 12(4.75,-0.635) 13(4.75,0.635) 14(4.75,1.905) 15(4.75,3.175) 16(4.75,4.445)
  silkscreen extent -5.6,-5.25 3.4,5.25, body extent -5.17,-5.15 5.17,5.15, height 2.59
FCC_disclaimer_stacked [mil]
Fiducial10-20 [mm]
  round 1 smd mask+0.5: 1(0,0)
  Top Layer keep-out circle w1.178: c0,0 r0.5
Keystone5000 [mil] "For Keystone 500x miniature loop terminals"
  round 80 hole 40: 1(0,0)
  silkscreen extent -58,-58 58,58, body extent -49,-49 49,49, height 182
Keystone5001 [mil] "For Keystone 500x miniature loop terminals"
  round 80 hole 40: 1(0,0)
  silkscreen extent -58,-58 58,58, body extent -49,-49 49,49, height 182
Keystone5002 [mil] "For Keystone 500x miniature loop terminals"
  round 80 hole 40: 1(0,0)
  silkscreen extent -58,-58 58,58, body extent -49,-49 49,49, height 182
Keystone5003 [mil] "For Keystone 500x miniature loop terminals"
  round 80 hole 40: 1(0,0)
  silkscreen extent -58,-58 58,58, body extent -49,-49 49,49, height 182
Keystone5004 [mil] "For Keystone 500x miniature loop terminals"
  round 80 hole 40: 1(0,0)
  silkscreen extent -58,-58 58,58, body extent -49,-49 49,49, height 182
"LB Q39G_BLUE" [mm] "OSRAM"
  rect 0.8x0.8 smd: 1(-0.75,0) 2(0.75,0)
  silkscreen extent 1.3,-0.5 1.52,0.5, body extent -0.85,-0.45 0.85,0.45, height 0.4
Major_BBB_SSHQ-123-D-08 [mm] "Female Connector, 2.54mm, 23x2, TH"
  rect 1.55x1.55 hole 1.02: 1(-27.94,-1.27)
  round 1.55 hole 1.02: 2(-27.94,1.27) 3(-25.4,-1.27) 4(-25.4,1.27) 5(-22.86,-1.27) 6(-22.86,1.27) 7(-20.32,-1.27) 8(-20.32,1.27) 9(-17.78,-1.27) 10(-17.78,1.27) 11(-15.24,-1.27) 12(-15.24,1.27) 13(-12.7,-1.27) 14(-12.7,1.27) 15(-10.16,-1.27) 16(-10.16,1.27) 17(-7.62,-1.27) 18(-7.62,1.27) 19(-5.08,-1.27) 20(-5.08,1.27) 21(-2.54,-1.27) 22(-2.54,1.27) 23(0,-1.27) 24(0,1.27) 25(2.54,-1.27) 26(2.54,1.27) 27(5.08,-1.27) 28(5.08,1.27) 29(7.62,-1.27) 30(7.62,1.27) 31(10.16,-1.27) 32(10.16,1.27) 33(12.7,-1.27) 34(12.7,1.27) 35(15.24,-1.27) 36(15.24,1.27) 37(17.78,-1.27) 38(17.78,1.27) 39(20.32,-1.27) 40(20.32,1.27) 41(22.86,-1.27) 42(22.86,1.27) 43(25.4,-1.27) 44(25.4,1.27) 45(27.94,-1.27) 46(27.94,1.27)
  silkscreen extent -29.53,-2.85 29.53,2.57, body extent -29.46,-2.51 29.46,2.51, height 8.51
MTGP_4-40_PanHead [mm] "4-40 Mounting Hole, Plated, for Pan Head"
  round 6.4 hole 3.5: 1(0,0)
Net-Tie_20milWide_60milLong [mil] "20mil net tie, no solder mask opening, no solder paste"
  rect 60x20 smd paste-10 mask-10: 1(-30,0) 2(30,0)
Pb-Free_Overlay_Small [mil]
  silkscreen extent -46,-46 46,46
Phoenix_1844333 [mm] "Header (Shrouded), 3.5mm, 14x1, R/A, TH"
  rect 1.7x1.7 hole 1.2: 1(8,22.75)
  round 1.7 hole 1.2: 2(8,19.25) 3(8,15.75) 4(8,12.25) 5(8,8.75) 6(8,5.25) 7(8,1.75) 8(8,-1.75) 9(8,-5.25) 10(8,-8.75) 11(8,-12.25) 12(8,-15.75) 13(8,-19.25) 14(8,-22.75)
  silkscreen extent 1,-25.2 10,25.2, body extent 0,-25.2 9.2,25.2, height 7.26
PW0016A_N [mm] "TSOP, 16-Leads, Body 5x4.4mm, Pitch 0.65mm, IPC Medium Density"
  oval 1.4x0.45 smd: 1(-2.95,2.275) 2(-2.95,1.625) 3(-2.95,0.975) 4(-2.95,0.325) 5(-2.95,-0.325) 6(-2.95,-0.975) 7(-2.95,-1.625) 8(-2.95,-2.275) 9(2.95,-2.275) 10(2.95,-1.625) 11(2.95,-0.975) 12(2.95,-0.325) 13(2.95,0.325) 14(2.95,0.975) 15(2.95,1.625) 16(2.95,2.275)
  silkscreen extent -3.5,-2.55 1.85,2.75, body extent -3.21,-2.5 3.21,2.5, height 1
RELAY_CPC1017N [mm] "SOP, 4-Lead, Body 4.089x3.81mm, Pitch 2.54mm"
  oval 1.3x0.6 smd: 1(-2.8,1.27) 2(-2.8,-1.27) 3(2.8,-1.27) 4(2.8,1.27)
  silkscreen extent -1.94,-2.15 1.94,2.4, body extent -1.94,-2.15 1.94,2.15, height 2.18
RTE0016F [mm] "Texas Insturments"
  rrect42% 0.6x0.24 smd: 1(-1.4,0.75) 2(-1.4,0.25) 3(-1.4,-0.25) 4(-1.4,-0.75) 9(1.4,-0.75) 10(1.4,-0.25) 11(1.4,0.25) 12(1.4,0.75)
  rrect42% 0.24x0.6 smd: 5(-0.75,-1.4) 6(-0.25,-1.4) 7(0.25,-1.4) 8(0.75,-1.4) 13(0.75,1.4) 14(0.25,1.4) 15(-0.25,1.4) 16(-0.75,1.4)
  rrect7% 1.5x1.5 on Top Paste: 17(0,0)
  rrect6% 1.65x1.65 smd paste-0.85: 17(0,0)
  silkscreen extent -1.72,-1.73 1.72,1.73, body extent -1.5,-1.5 1.5,1.5, height 0.8
SMA [mm] "Molded Diode, 2-Leads, Body 4.3x2.6mm, IPC Medium Density, based on OnSemi component dimensions and land pattern"
  rect 2x2 smd: 1(-2,0) 2(2,0)
  silkscreen extent -3.66,-1.57 2.79,1.57, body extent -2.6,-1.3 2.6,1.3, height 2.42
SMB-Bi [mil] "Molded Diode, 2-Leads, Body 5.4x3.6mm, IPC Medium Density, based on OnSemi component dimensions"
  rect 85x107.99 smd: 1(-87.01,0) 2(87.01,0)
  silkscreen extent -125,-79 125,79, body extent -104,-73 104,73, height 89
SOD-123 [mm] "On Semi recommended land pattern"
  rect 0.915x1.22 smd: 1(-1.637,0) 2(1.637,0)
  silkscreen extent -2.74,-1.17 2.03,1.17, body extent -1.93,-0.9 1.93,0.9, height 1.35
SW_416131160802 [mm] "SMD, 4-Leads, Body 5.6x3.58mm, Pitch 1.27mm"
  rect 1.27x0.76 smd: 1(-3.81,0.635) 2(-3.81,-0.635) 3(3.81,-0.635) 4(3.81,0.635)
  silkscreen extent -2.8,-1.79 2.8,2.1, body extent -4,-1.79 4,1.79, height 2.1
TE_5-146278-3 [mm] "TE CONNECTIVITY"
  rect 1.65x1.65 hole 1: 1(-2.54,0)
  round 1.65 hole 1: 2(0,0) 3(2.54,0)
  silkscreen extent -4.19,-1.27 3.81,1.27, body extent -3.68,-1.17 3.68,1.17, height 8.13
TESTPOINT [mil]
  round 80 hole 37.99: 1(0,0)
TSSOP-8 [mm] "TSSOP, 8-Leads, Body 3.1x4.5mm (max), Pitch 0.65mm, IPC Medium Density"
  rrect50% 1.7x0.35 smd: 1(-2.85,0.975) 2(-2.85,0.325) 3(-2.85,-0.325) 4(-2.85,-0.975) 5(2.85,-0.975) 6(2.85,-0.325) 7(2.85,0.325) 8(2.85,0.975)
  silkscreen extent -2.98,-1.55 1.6,1.82, body extent -3.2,-1.55 3.2,1.55, height 1.07
Wurth_750316170 [mm] "SMT, 8-Leads, Body 9.5x9.78mm, Pitch 2.49mm"
  rect 1.17x1.91 smd: 1(-3.735,4.065) 2(-1.245,4.065) 3(1.245,4.065) 4(3.735,4.065) 5(3.735,-4.065) 6(1.245,-4.065) 7(-1.245,-4.065) 8(-3.735,-4.065)
  silkscreen extent -5.3,-3.5 4.89,3.6, body extent -4.89,-4.75 4.89,4.75, height 10.54
Wurth_60900213421 [mil] "Shunt, 2.54mm, Black"
  round 1 on Mech3: 0(0,0)
  body extent -98,-48 98,48, height 236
